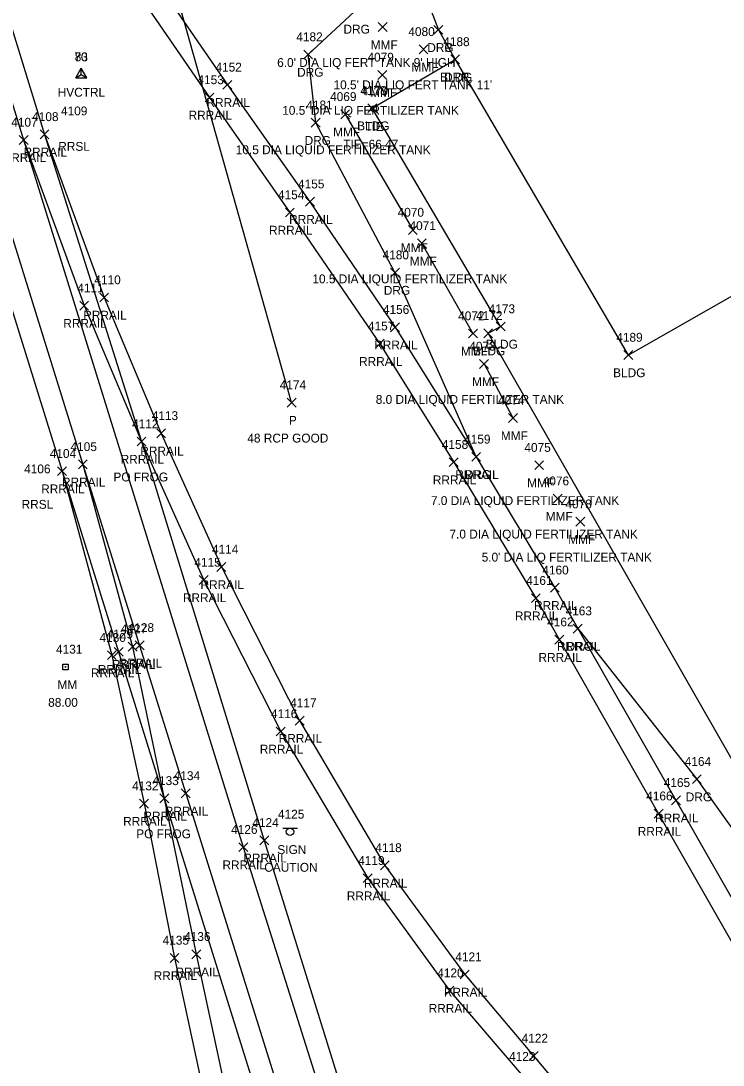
# Model space of a CAD drawing. Extents: x 1462668 to 1465147, y 550359 to 557351.
# Drawn here: x 1463558.8 to 1463717.3, y 555842.9 to 556078.6 of the extents above; entities that cross this region are included whole.
import ezdxf

# ---------------------------------------------------------------- set-up
doc = ezdxf.new("R2010")
doc.units = 0
for name, color, linetype in [('C_A', 7, 'Continuous'), ('C_C', 7, 'Continuous'), ('C_I', 7, 'Continuous'), ('CBP', 7, 'Continuous'), ('CPSM', 7, 'Continuous'), ('D_A', 7, 'Continuous'), ('D_C', 7, 'Continuous'), ('D_I', 7, 'Continuous'), ('D_TIC', 7, 'Continuous'), ('DCP', 7, 'Continuous'), ('L_A', 7, 'Continuous'), ('L_C', 7, 'Continuous'), ('L_I', 7, 'Continuous'), ('L_TIC', 7, 'Continuous'), ('LBC', 7, 'Continuous'), ('LDEFAULT', 7, 'Continuous'), ('R_A', 7, 'Continuous'), ('R_C', 7, 'Continuous'), ('R_I', 7, 'Continuous'), ('R_TIC', 7, 'Continuous'), ('RDG', 7, 'Continuous'), ('RDP', 7, 'Continuous'), ('RR', 7, 'Continuous'), ('S_A', 7, 'Continuous'), ('S_C', 7, 'Continuous'), ('S_I', 7, 'Continuous'), ('SRM', 7, 'Continuous'), ('SSGN', 7, 'Continuous')]:
    doc.layers.add(name, color=color, linetype=linetype)

msp = doc.modelspace()

# ---------------------------------------------------------------- linework, layer by layer
at = {"layer": 'CBP'}
for radius in [0.625, 0.0833]:
    msp.add_circle((1463638.46, 556058.77), radius, dxfattribs=at)
at = {"layer": 'CPSM'}
for p, q in [((1463571.2, 556065.76), (1463572.45, 556067.93)), ((1463571.2, 556065.76), (1463572.45, 556067.92)), ((1463573.7, 556065.76), (1463572.45, 556067.93)), ((1463572.45, 556066.48), (1463572.45, 556067.93)), ((1463573.7, 556065.76), (1463572.45, 556067.92)), ((1463572.45, 556066.48), (1463572.45, 556067.92)), ((1463571.2, 556065.76), (1463572.45, 556066.48)), ((1463571.2, 556065.76), (1463572.45, 556066.48)), ((1463571.2, 556065.76), (1463573.7, 556065.76)), ((1463571.2, 556065.76), (1463573.7, 556065.76)), ((1463572.45, 556066.48), (1463572.45, 556066.48)), ((1463572.45, 556066.48), (1463573.7, 556065.76)), ((1463572.45, 556066.48), (1463572.45, 556066.48)), ((1463572.45, 556066.48), (1463573.7, 556065.76))]:
    msp.add_line(p, q, dxfattribs=at)
at = {"layer": 'D_TIC'}
for points in [[(1463618.95, 555991.43), (1463620.95, 555993.43)], [(1463620.95, 555991.43), (1463618.95, 555993.43)]]:
    msp.add_lwpolyline(points, dxfattribs=at)
at = {"layer": 'DCP'}
msp.add_lwpolyline([(1463619.95, 555992.43), (1463572.02, 556162.72)], dxfattribs=at)
at = {"layer": 'L_TIC'}
for points in [[(1463639.5, 556076.2), (1463641.5, 556078.2)], [(1463641.5, 556076.2), (1463639.5, 556078.2)], [(1463648.71, 556071.17), (1463650.71, 556073.17)], [(1463650.71, 556071.17), (1463648.71, 556073.17)], [(1463655.86, 556068.9), (1463657.86, 556070.9)], [(1463657.86, 556068.9), (1463655.86, 556070.9)], [(1463639.41, 556065.4), (1463641.41, 556067.4)], [(1463641.41, 556065.4), (1463639.41, 556067.4)], [(1463637.14, 556057.9), (1463639.14, 556059.9)], [(1463639.14, 556057.9), (1463637.14, 556059.9)], [(1463631.02, 556056.51), (1463633.02, 556058.51)], [(1463633.02, 556056.51), (1463631.02, 556058.51)], [(1463646.29, 556030.4), (1463648.29, 556032.4)], [(1463648.29, 556030.4), (1463646.29, 556032.4)], [(1463648.33, 556027.37), (1463650.33, 556029.37)], [(1463650.33, 556027.37), (1463648.33, 556029.37)], [(1463666.12, 556008.62), (1463668.12, 556010.62)], [(1463668.12, 556008.62), (1463666.12, 556010.62)], [(1463659.86, 556007.03), (1463661.86, 556009.03)], [(1463661.86, 556007.03), (1463659.86, 556009.03)], [(1463663.29, 556007.09), (1463665.29, 556009.09)], [(1463665.29, 556007.09), (1463663.29, 556009.09)], [(1463694.92, 556002.18), (1463696.92, 556004.18)], [(1463696.92, 556002.18), (1463694.92, 556004.18)], [(1463662.37, 556000.16), (1463664.37, 556002.16)], [(1463664.37, 556000.16), (1463662.37, 556002.16)], [(1463668.89, 555987.97), (1463670.89, 555989.97)], [(1463670.89, 555987.97), (1463668.89, 555989.97)], [(1463674.82, 555977.32), (1463676.82, 555979.32)], [(1463676.82, 555977.32), (1463674.82, 555979.32)], [(1463679.01, 555969.76), (1463681.01, 555971.76)], [(1463681.01, 555969.76), (1463679.01, 555971.76)], [(1463684.09, 555964.56), (1463686.09, 555966.56)], [(1463686.09, 555964.56), (1463684.09, 555966.56)]]:
    msp.add_lwpolyline(points, dxfattribs=at)
at = {"layer": 'LBC'}
msp.add_lwpolyline([(1463735.88, 555882.97), (1463664.29, 556008.09), (1463667.12, 556009.62), (1463638.14, 556058.9), (1463656.86, 556069.9), (1463695.92, 556003.18), (1463723.21, 556018.72), (1463765.13, 555945.62), (1463755.09, 555939.6), (1463774.68, 555905.08)], dxfattribs=at)
at = {"layer": 'LDEFAULT'}
for points in [[(1463632.02, 556057.51), (1463647.29, 556031.4)], [(1463649.33, 556028.37), (1463660.86, 556008.03)], [(1463663.37, 556001.16), (1463669.89, 555988.97)]]:
    msp.add_lwpolyline(points, dxfattribs=at)
at = {"layer": 'R_TIC'}
for points in [[(1463652.07, 556075.57), (1463654.07, 556077.57)], [(1463654.07, 556075.57), (1463652.07, 556077.57)], [(1463652.07, 556075.57), (1463654.07, 556077.57)], [(1463654.07, 556075.57), (1463652.07, 556077.57)], [(1463622.69, 556070), (1463624.69, 556072)], [(1463624.69, 556070), (1463622.69, 556072)], [(1463655.86, 556068.9), (1463657.86, 556070.9)], [(1463657.86, 556068.9), (1463655.86, 556070.9)], [(1463604.44, 556063.16), (1463606.44, 556065.16)], [(1463606.44, 556063.16), (1463604.44, 556065.16)], [(1463600.39, 556060.32), (1463602.39, 556062.32)], [(1463602.39, 556060.32), (1463600.39, 556062.32)], [(1463624.39, 556054.61), (1463626.39, 556056.61)], [(1463626.39, 556054.61), (1463624.39, 556056.61)], [(1463558.44, 556050.72), (1463560.44, 556052.72)], [(1463560.44, 556050.72), (1463558.44, 556052.72)], [(1463558.44, 556050.72), (1463560.44, 556052.72)], [(1463560.44, 556050.72), (1463558.44, 556052.72)], [(1463563.15, 556051.98), (1463565.15, 556053.98)], [(1463565.15, 556051.98), (1463563.15, 556053.98)], [(1463563.15, 556051.98), (1463565.15, 556053.98)], [(1463565.15, 556051.98), (1463563.15, 556053.98)], [(1463623.08, 556036.79), (1463625.08, 556038.79)], [(1463625.08, 556036.79), (1463623.08, 556038.79)], [(1463618.55, 556034.35), (1463620.55, 556036.35)], [(1463620.55, 556034.35), (1463618.55, 556036.35)], [(1463642.26, 556020.78), (1463644.26, 556022.78)], [(1463644.26, 556020.78), (1463642.26, 556022.78)], [(1463572.12, 556013.32), (1463574.12, 556015.32)], [(1463574.12, 556013.32), (1463572.12, 556015.32)], [(1463576.63, 556015.16), (1463578.63, 556017.16)], [(1463578.63, 556015.16), (1463576.63, 556017.16)], [(1463642.29, 556008.45), (1463644.29, 556010.45)], [(1463644.29, 556008.45), (1463642.29, 556010.45)], [(1463638.86, 556004.73), (1463640.86, 556006.73)], [(1463640.86, 556004.73), (1463638.86, 556006.73)], [(1463585.06, 555982.65), (1463587.06, 555984.65)], [(1463587.06, 555982.65), (1463585.06, 555984.65)], [(1463585.06, 555982.65), (1463587.06, 555984.65)], [(1463587.06, 555982.65), (1463585.06, 555984.65)], [(1463589.5, 555984.5), (1463591.5, 555986.5)], [(1463591.5, 555984.5), (1463589.5, 555986.5)], [(1463571.82, 555977.5), (1463573.82, 555979.5)], [(1463573.82, 555977.5), (1463571.82, 555979.5)], [(1463571.82, 555977.5), (1463573.82, 555979.5)], [(1463573.82, 555977.5), (1463571.82, 555979.5)], [(1463655.53, 555977.99), (1463657.53, 555979.99)], [(1463657.53, 555977.99), (1463655.53, 555979.99)], [(1463660.58, 555979.19), (1463662.58, 555981.19)], [(1463662.58, 555979.19), (1463660.58, 555981.19)], [(1463660.58, 555979.19), (1463662.58, 555981.19)], [(1463662.58, 555979.19), (1463660.58, 555981.19)], [(1463567.13, 555975.96), (1463569.13, 555977.96)], [(1463569.13, 555975.96), (1463567.13, 555977.96)], [(1463567.13, 555975.96), (1463569.13, 555977.96)], [(1463569.13, 555975.96), (1463567.13, 555977.96)], [(1463603.09, 555954.34), (1463605.09, 555956.34)], [(1463605.09, 555954.34), (1463603.09, 555956.34)], [(1463599.11, 555951.4), (1463601.11, 555953.4)], [(1463601.11, 555951.4), (1463599.11, 555953.4)], [(1463678.36, 555949.65), (1463680.36, 555951.65)], [(1463680.36, 555949.65), (1463678.36, 555951.65)], [(1463674.05, 555947.3), (1463676.05, 555949.3)], [(1463676.05, 555947.3), (1463674.05, 555949.3)], [(1463683.52, 555940.43), (1463685.52, 555942.43)], [(1463685.52, 555940.43), (1463683.52, 555942.43)], [(1463683.52, 555940.43), (1463685.52, 555942.43)], [(1463685.52, 555940.43), (1463683.52, 555942.43)], [(1463679.37, 555937.93), (1463681.37, 555939.93)], [(1463681.37, 555937.93), (1463679.37, 555939.93)], [(1463579.9, 555935.2), (1463581.9, 555937.2)], [(1463581.9, 555935.2), (1463579.9, 555937.2)], [(1463583.06, 555936.35), (1463585.06, 555938.35)], [(1463585.06, 555936.35), (1463583.06, 555938.35)], [(1463584.63, 555936.65), (1463586.63, 555938.65)], [(1463586.63, 555936.65), (1463584.63, 555938.65)], [(1463578.35, 555934.43), (1463580.35, 555936.43)], [(1463580.35, 555934.43), (1463578.35, 555936.43)], [(1463620.74, 555919.66), (1463622.74, 555921.66)], [(1463622.74, 555919.66), (1463620.74, 555921.66)], [(1463616.47, 555917.22), (1463618.47, 555919.22)], [(1463618.47, 555917.22), (1463616.47, 555919.22)], [(1463710.41, 555906.45), (1463712.41, 555908.45)], [(1463712.41, 555906.45), (1463710.41, 555908.45)], [(1463590.21, 555902.11), (1463592.21, 555904.11)], [(1463592.21, 555902.11), (1463590.21, 555904.11)], [(1463590.21, 555902.11), (1463592.21, 555904.11)], [(1463592.21, 555902.11), (1463590.21, 555904.11)], [(1463595.03, 555903.23), (1463597.03, 555905.23)], [(1463597.03, 555903.23), (1463595.03, 555905.23)], [(1463585.63, 555900.93), (1463587.63, 555902.93)], [(1463587.63, 555900.93), (1463585.63, 555902.93)], [(1463705.68, 555901.68), (1463707.68, 555903.68)], [(1463707.68, 555901.68), (1463705.68, 555903.68)], [(1463701.78, 555898.66), (1463703.78, 555900.66)], [(1463703.78, 555898.66), (1463701.78, 555900.66)], [(1463612.76, 555892.64), (1463614.76, 555894.64)], [(1463614.76, 555892.64), (1463612.76, 555894.64)], [(1463608.03, 555891.1), (1463610.03, 555893.1)], [(1463610.03, 555891.1), (1463608.03, 555893.1)], [(1463639.97, 555886.98), (1463641.97, 555888.98)], [(1463641.97, 555886.98), (1463639.97, 555888.98)], [(1463636.11, 555884.1), (1463638.11, 555886.1)], [(1463638.11, 555884.1), (1463636.11, 555886.1)], [(1463597.42, 555866.93), (1463599.42, 555868.93)], [(1463599.42, 555866.93), (1463597.42, 555868.93)], [(1463592.51, 555866.09), (1463594.51, 555868.09)], [(1463594.51, 555866.09), (1463592.51, 555868.09)], [(1463658.02, 555862.36), (1463660.02, 555864.36)], [(1463660.02, 555862.36), (1463658.02, 555864.36)], [(1463654.59, 555858.72), (1463656.59, 555860.72)], [(1463656.59, 555858.72), (1463654.59, 555860.72)], [(1463673.56, 555843.98), (1463675.56, 555845.98)], [(1463675.56, 555843.98), (1463673.56, 555845.98)]]:
    msp.add_lwpolyline(points, dxfattribs=at)
at = {"layer": 'RDG'}
for points in [[(1463661.58, 555980.19), (1463643.26, 556021.78), (1463625.39, 556055.61), (1463623.69, 556071), (1463634.16, 556080.73), (1463649.63, 556085.6), (1463653.07, 556076.57)], [(1463684.52, 555941.43), (1463711.41, 555907.45), (1463739.02, 555868.77), (1463762.1, 555845.45), (1463788.4, 555849.97)]]:
    msp.add_lwpolyline(points, dxfattribs=at)
at = {"layer": 'RDP'}
msp.add_lwpolyline([(1463653.07, 556076.57), (1463656.86, 556069.9)], dxfattribs=at)
at = {"layer": 'RR'}
for points in [[(1463452.29, 556399.95), (1463497.45, 556252.55), (1463536.87, 556125.13), (1463559.44, 556051.72), (1463609.03, 555892.1), (1463628.98, 555828.76), (1463638.23, 555801.69), (1463650.08, 555771.85), (1463660.17, 555749.93), (1463672.27, 555721.97), (1463682.4, 555694.55), (1463717.94, 555583.41), (1463735.76, 555525.64), (1463763.54, 555435.87), (1463784.43, 555367.81), (1463820.27, 555252.31), (1463843.81, 555175.84), (1463843.97, 555175.21), (1463873.04, 555081.28), (1463903.09, 554986.35)], [(1463457.08, 556400.94), (1463502.23, 556254.01), (1463520.47, 556194.57), (1463541.51, 556126.54), (1463564.15, 556052.98), (1463586.06, 555983.65), (1463613.76, 555893.64), (1463633.52, 555829.96), (1463642.44, 555804.5), (1463654.17, 555774.55), (1463664.49, 555752.05), (1463676.6, 555724.22), (1463687.08, 555696.18), (1463722.45, 555584.97), (1463740.37, 555527.27), (1463768.14, 555437.45), (1463788.82, 555369.5), (1463824.75, 555254.42), (1463848.38, 555177.53), (1463848.44, 555177), (1463877.95, 555082.45), (1463907.74, 554987.88)], [(1463442.74, 556395.94), (1463488.6, 556249.11), (1463529.74, 556117.02), (1463572.82, 555978.5), (1463585.63, 555937.65), (1463596.03, 555904.23), (1463633.49, 555784.66), (1463672.64, 555658.35), (1463710.59, 555536.66), (1463747.52, 555418.1), (1463780.06, 555313.88), (1463826.09, 555167.8), (1463825.99, 555167.57), (1463854.77, 555075.73), (1463884.96, 554978.2)], [(1463438.37, 556393.48), (1463483.91, 556247.77), (1463525.3, 556114.77), (1463568.13, 555976.96), (1463580.9, 555936.2), (1463591.21, 555903.11), (1463628.7, 555782.9), (1463668.19, 555656.69), (1463705.56, 555535.16), (1463742.77, 555417.12), (1463775.39, 555312.32), (1463821.31, 555166.17), (1463821.55, 555165.37), (1463850.06, 555074.38), (1463880.04, 554977.58)], [(1463502.23, 556254.01), (1463511.19, 556228.25), (1463525, 556196.56), (1463542.23, 556162.53), (1463557.71, 556135.12), (1463575.23, 556108.11), (1463605.44, 556064.16), (1463624.08, 556037.79), (1463643.29, 556009.45), (1463661.58, 555980.19), (1463679.36, 555950.65), (1463684.52, 555941.43), (1463706.68, 555902.68), (1463743.99, 555837.35), (1463791.88, 555753.25)], [(1463497.45, 556252.55), (1463506.7, 556226.15), (1463520.47, 556194.57), (1463538.36, 556159.3), (1463553.64, 556132.52), (1463571.22, 556105.26), (1463601.39, 556061.32), (1463619.55, 556035.35), (1463639.86, 556005.73), (1463656.53, 555978.99), (1463675.05, 555948.3), (1463680.37, 555938.93), (1463702.78, 555899.66), (1463740.34, 555833.79), (1463787.29, 555751.17)], [(1463564.15, 556052.98), (1463577.63, 556016.16), (1463590.5, 555985.5), (1463604.09, 555955.34), (1463621.74, 555920.66), (1463640.97, 555887.98), (1463659.02, 555863.36), (1463674.56, 555844.98), (1463790.76, 555706.47), (1463812.34, 555667.12), (1463842, 555611.41), (1463880.6, 555538.7), (1463906.31, 555490.4), (1463925.67, 555454.53), (1463964.21, 555382.49), (1463992.77, 555329.44)], [(1463559.44, 556051.72), (1463573.12, 556014.32), (1463586.06, 555983.65), (1463600.11, 555952.4), (1463617.47, 555918.22), (1463637.11, 555885.1), (1463655.59, 555859.72), (1463671.73, 555840.87), (1463786.15, 555704.35), (1463807.99, 555664.91), (1463837.51, 555609.05), (1463871.83, 555544.68), (1463902.36, 555487.74), (1463921.15, 555452.57), (1463959.81, 555380.31), (1463988.19, 555327.21)], [(1463572.82, 555978.5), (1463584.06, 555937.35), (1463591.21, 555903.11), (1463598.42, 555867.93), (1463607.06, 555827.71), (1463619.3, 555782.42), (1463659.27, 555654.72), (1463696.5, 555533.57), (1463734.29, 555414.51), (1463767.42, 555309.25), (1463798.97, 555209.76)], [(1463568.13, 555976.96), (1463579.35, 555935.43), (1463586.63, 555901.93), (1463593.51, 555867.09), (1463602.3, 555826.27), (1463614.8, 555780.19), (1463654.9, 555652.54), (1463702.04, 555501.01), (1463726.18, 555423.83), (1463744.37, 555366.2), (1463775.2, 555267.76), (1463794.28, 555208.18)]]:
    msp.add_lwpolyline(points, dxfattribs=at)
at = {"layer": 'SRM'}
msp.add_lwpolyline([(1463568.27, 555933.41), (1463569.52, 555933.41), (1463569.52, 555932.16), (1463568.27, 555932.16)], close=True, dxfattribs=at)
msp.add_circle((1463568.9, 555932.78), 0.0833, dxfattribs=at)
at = {"layer": 'SSGN'}
for p, q in [((1463617.93, 555896.41), (1463621.26, 555896.41)), ((1463619.58, 555895.58), (1463619.58, 555895.58))]:
    msp.add_line(p, q, dxfattribs=at)
msp.add_circle((1463619.58, 555895.58), 0.833, dxfattribs=at)

# ---------------------------------------------------------------- texts
at = {"layer": 'C_A'}
for s, p in [('HVCTRL', (1463567.14, 556061.48)), ('HVCTRL', (1463567.15, 556061.48)), ('TIE', (1463636.54, 556053.77))]:
    msp.add_text(s, height=2, dxfattribs=at).set_placement(p)
at = {"layer": 'C_C'}
msp.add_text('TIE=66.47', height=2, dxfattribs=at).set_placement((1463631.6, 556049.77))
at = {"layer": 'C_I'}
for s, p in [('70', (1463570.9, 556069.48)), ('83', (1463570.99, 556069.48)), ('4179', (1463635.76, 556061.77))]:
    msp.add_text(s, height=2, dxfattribs=at).set_placement(p)
at = {"layer": 'D_A'}
msp.add_text('P', height=2, dxfattribs=at).set_placement((1463619.32, 555987.43))
at = {"layer": 'D_C'}
msp.add_text('48 RCP GOOD', height=2, dxfattribs=at).set_placement((1463609.95, 555983.43))
at = {"layer": 'D_I'}
msp.add_text('4174', height=2, dxfattribs=at).set_placement((1463617.25, 555995.43))
at = {"layer": 'L_A'}
for s, p in [('MMF', (1463637.79, 556072.2)), ('MMF', (1463647, 556067.17)), ('BLDG', (1463653.45, 556064.9)), ('MMF', (1463637.69, 556061.4)), ('BLDG', (1463634.73, 556053.9)), ('MMF', (1463629.31, 556052.51)), ('MMF', (1463644.57, 556026.4)), ('MMF', (1463646.61, 556023.37)), ('BLDG', (1463663.71, 556004.62)), ('MMF', (1463658.15, 556003.03)), ('BLDG', (1463660.88, 556003.09)), ('BLDG', (1463692.51, 555998.18)), ('MMF', (1463660.66, 555996.16)), ('MMF', (1463667.17, 555983.97)), ('MMF', (1463673.11, 555973.32)), ('MMF', (1463677.29, 555965.76)), ('MMF', (1463682.37, 555960.56))]:
    msp.add_text(s, height=2, dxfattribs=at).set_placement(p)
at = {"layer": 'L_C'}
for s, p in [("6.0' DIA LIQ FERT TANK 9' HIGH", (1463616.68, 556068.2)), ("10.5' DIA LIQ FERT TANK 11'", (1463629.4, 556063.17)), ("10.5' DIA LIQ FERTILIZER TANK", (1463617.82, 556057.4)), ('10.5 DIA LIQUID FERTILIZER TANK', (1463607.33, 556048.51)), ('10.5 DIA LIQUID FERTILIZER TANK', (1463624.63, 556019.37)), ('8.0 DIA LIQUID FERTILIZER TANK', (1463638.93, 555992.16)), ('7.0 DIA LIQUID FERTILIZER TANK', (1463651.38, 555969.32)), ('7.0 DIA LIQUID FERTILIZER TANK', (1463655.57, 555961.76)), ("5.0' DIA LIQ FERTILIZER TANK", (1463662.84, 555956.56))]:
    msp.add_text(s, height=2, dxfattribs=at).set_placement(p)
at = {"layer": 'L_I'}
for s, p in [('4080', (1463646.29, 556075.17)), ('4188', (1463654.17, 556072.9)), ('4079', (1463637.06, 556069.4)), ('4069', (1463628.63, 556060.51)), ('4178', (1463635.44, 556061.9)), ('4070', (1463643.87, 556034.4)), ('4071', (1463646.55, 556031.37)), ('4072', (1463657.53, 556011.03)), ('4172', (1463661.59, 556011.09)), ('4173', (1463664.42, 556012.62)), ('4189', (1463693.22, 556006.18)), ('4073', (1463660.04, 556004.16)), ('4074', (1463666.55, 555991.97)), ('4075', (1463672.48, 555981.32)), ('4076', (1463676.62, 555973.76)), ('4078', (1463681.75, 555968.56))]:
    msp.add_text(s, height=2, dxfattribs=at).set_placement(p)
at = {"layer": 'R_A'}
for s, p in [('DRG', (1463631.65, 556075.73)), ('DRG', (1463650.56, 556071.57)), ('DRP', (1463650.56, 556071.57)), ('DRG', (1463621.18, 556066)), ('DRP', (1463654.35, 556064.9)), ('RRRAIL', (1463600.73, 556059.16)), ('RRRAIL', (1463596.68, 556056.32)), ('DRG', (1463622.88, 556050.61)), ('RRSL', (1463567.27, 556049.27)), ('RRRAIL', (1463554.73, 556046.72)), ('RRRAIL', (1463554.73, 556046.72)), ('RRRAIL', (1463559.44, 556047.98)), ('RRRAIL', (1463559.44, 556047.98)), ('RRRAIL', (1463619.38, 556032.79)), ('RRRAIL', (1463614.84, 556030.35)), ('DRG', (1463640.75, 556016.78)), ('RRRAIL', (1463572.92, 556011.16)), ('RRRAIL', (1463568.41, 556009.32)), ('RRRAIL', (1463638.58, 556004.45)), ('RRRAIL', (1463635.16, 556000.73)), ('RRRAIL', (1463585.79, 555980.5)), ('RRRAIL', (1463581.35, 555978.65)), ('RRRAIL', (1463581.35, 555978.65)), ('RRRAIL', (1463656.87, 555975.19)), ('DRG', (1463659.07, 555975.19)), ('RRRAIL', (1463568.11, 555973.5)), ('RRRAIL', (1463568.11, 555973.5)), ('RRRAIL', (1463651.82, 555973.99)), ('RRRAIL', (1463563.42, 555971.96)), ('RRRAIL', (1463563.42, 555971.96)), ('RRSL', (1463559, 555968.48)), ('RRRAIL', (1463599.38, 555950.34)), ('RRRAIL', (1463595.4, 555947.4)), ('RRRAIL', (1463674.65, 555945.65)), ('RRRAIL', (1463670.34, 555943.3)), ('RRRAIL', (1463679.82, 555936.43)), ('DRG', (1463682.01, 555936.43)), ('RRRAIL', (1463675.66, 555933.93)), ('RRRAIL', (1463574.64, 555930.43)), ('RRRAIL', (1463576.19, 555931.2)), ('RRRAIL', (1463579.36, 555932.35)), ('RRRAIL', (1463580.92, 555932.65)), ('RRRAIL', (1463617.03, 555915.66)), ('RRRAIL', (1463612.76, 555913.22)), ('DRG', (1463708.9, 555902.45)), ('RRRAIL', (1463586.5, 555898.11)), ('RRRAIL', (1463586.5, 555898.11)), ('RRRAIL', (1463591.32, 555899.23)), ('RRRAIL', (1463701.97, 555897.68)), ('RRRAIL', (1463581.92, 555896.93)), ('RRRAIL', (1463698.07, 555894.66)), ('RRRAIL', (1463609.05, 555888.64)), ('RRRAIL', (1463604.33, 555887.1)), ('RRRAIL', (1463636.26, 555882.98)), ('RRRAIL', (1463632.4, 555880.1)), ('RRRAIL', (1463588.8, 555862.09)), ('RRRAIL', (1463593.72, 555862.93)), ('RRRAIL', (1463654.31, 555858.36)), ('RRRAIL', (1463650.88, 555854.72))]:
    msp.add_text(s, height=2, dxfattribs=at).set_placement(p)
at = {"layer": 'R_C'}
for p in [(1463579.72, 555974.65), (1463579.72, 555974.65), (1463584.87, 555894.11), (1463584.87, 555894.11)]:
    msp.add_text('PO FROG', height=2, dxfattribs=at).set_placement(p)
at = {"layer": 'R_I'}
for s, p in [('4182', (1463621, 556074)), ('4188', (1463654.17, 556072.9)), ('4152', (1463602.75, 556067.16)), ('4153', (1463598.69, 556064.32)), ('4181', (1463623.27, 556058.61)), ('4108', (1463561.38, 556055.98)), ('4108', (1463561.38, 556055.98)), ('4109', (1463567.89, 556057.27)), ('4107', (1463556.66, 556054.72)), ('4107', (1463556.66, 556054.72)), ('4155', (1463621.39, 556040.79)), ('4154', (1463616.86, 556038.35)), ('4180', (1463640.48, 556024.78)), ('4110', (1463575.42, 556019.16)), ('4111', (1463571.56, 556017.32)), ('4156', (1463640.55, 556012.45)), ('4157', (1463637.17, 556008.73)), ('4113', (1463588.37, 555988.5)), ('4112', (1463583.93, 555986.65)), ('4112', (1463583.93, 555986.65)), ('4159', (1463658.88, 555983.19)), ('4159', (1463658.88, 555983.19)), ('4104', (1463565.36, 555979.96)), ('4104', (1463565.36, 555979.96)), ('4105', (1463570.04, 555981.5)), ('4105', (1463570.04, 555981.5)), ('4158', (1463653.84, 555981.99)), ('4106', (1463559.57, 555976.48)), ('4114', (1463601.96, 555958.34)), ('4115', (1463597.99, 555955.4)), ('4160', (1463676.53, 555953.65)), ('4161', (1463672.88, 555951.3)), ('4163', (1463681.78, 555944.43)), ('4163', (1463681.78, 555944.43)), ('4127', (1463581.37, 555940.35)), ('4128', (1463582.94, 555940.65)), ('4162', (1463677.63, 555941.93)), ('4130', (1463576.57, 555938.43)), ('4129', (1463578.2, 555939.2)), ('4117', (1463619.61, 555923.66)), ('4116', (1463615.29, 555921.22)), ('4164', (1463708.67, 555910.45)), ('4134', (1463593.33, 555907.23)), ('4132', (1463583.94, 555904.93)), ('4133', (1463588.52, 555906.11)), ('4133', (1463588.52, 555906.11)), ('4165', (1463703.94, 555905.68)), ('4166', (1463699.98, 555902.66)), ('4126', (1463606.29, 555895.1)), ('4124', (1463611.07, 555896.64)), ('4118', (1463638.84, 555890.98)), ('4119', (1463634.97, 555888.1)), ('4135', (1463590.82, 555870.09)), ('4136', (1463595.68, 555870.93)), ('4121', (1463656.9, 555866.36)), ('4120', (1463652.81, 555862.72)), ('4122', (1463671.86, 555847.98)), ('4123', (1463669.03, 555843.87))]:
    msp.add_text(s, height=2, dxfattribs=at).set_placement(p)
at = {"layer": 'S_A'}
for s, p in [('MM', (1463567.09, 555927.78)), ('SIGN', (1463616.72, 555890.55))]:
    msp.add_text(s, height=2, dxfattribs=at).set_placement(p)
at = {"layer": 'S_C'}
for s, p in [('88.00', (1463564.99, 555923.78)), ('CAUTION', (1463613.77, 555886.55))]:
    msp.add_text(s, height=2, dxfattribs=at).set_placement(p)
at = {"layer": 'S_I'}
for s, p in [('4131', (1463566.77, 555935.78)), ('4125', (1463616.86, 555898.55))]:
    msp.add_text(s, height=2, dxfattribs=at).set_placement(p)

doc.saveas('drawing.dxf')
